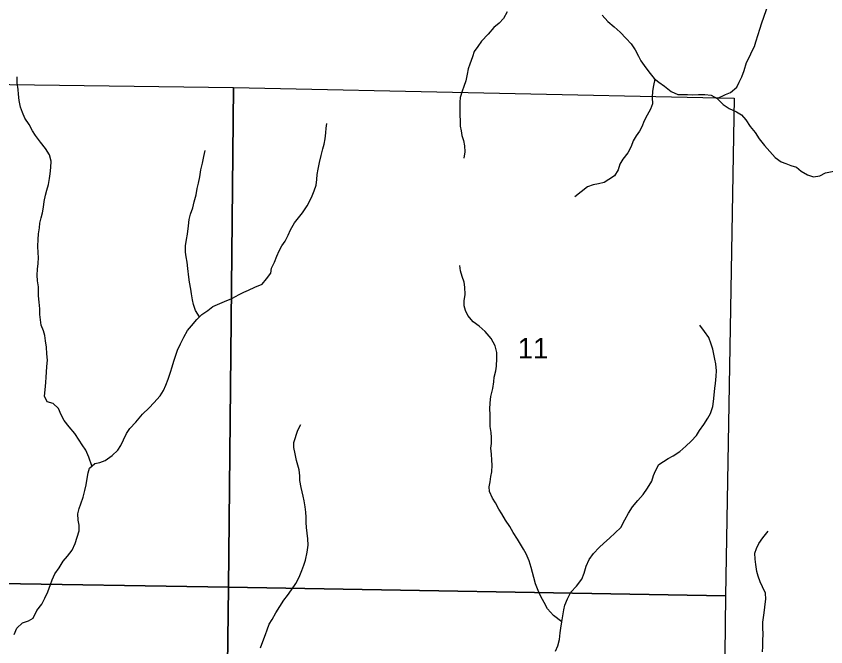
# Model space of a CAD drawing. Extents: x -10 to 158, y 8 to 33.
# Drawn here: x 27.203 to 28.851, y 17.335 to 18.62 of the extents above; entities that cross this region are included whole.
import ezdxf

# ---------------------------------------------------------------- set-up
doc = ezdxf.new("R2010")
doc.units = 0
for name, color, linetype in [('GM_X_Corporation', 7, 'Continuous'), ('GM_X_Minor_River', 7, 'Continuous'), ('GM_X_Section_Text', 7, 'Continuous')]:
    doc.layers.add(name, color=color, linetype=linetype)

msp = doc.modelspace()

# ---------------------------------------------------------------- linework, layer by layer
at = {"layer": 'GM_X_Corporation'}
for points in [[(26.6319, 18.4884), (27.6454, 18.4748), (27.6353, 17.4572), (26.6176, 17.4733)], [(27.6454, 18.4748), (28.6644, 18.4533), (28.647, 17.4394), (27.6353, 17.4572)], [(26.6176, 17.4733), (27.6353, 17.4572), (27.622, 16.4497), (26.6025, 16.4586)], [(27.6353, 17.4572), (28.647, 17.4394), (28.6357, 16.427), (27.622, 16.4497)]]:
    msp.add_lwpolyline(points, close=True, dxfattribs=at)
at = {"layer": 'GM_X_Minor_River'}
for points in [[(28.6301, 18.4525), (28.6472, 18.4605), (28.657, 18.4647), (28.6699, 18.4758), (28.6752, 18.4861), (28.6805, 18.4967), (28.6854, 18.5097), (28.6899, 18.5257), (28.6967, 18.5386), (28.7008, 18.5485), (28.7058, 18.5588), (28.7088, 18.5683), (28.7137, 18.5827), (28.717, 18.5941), (28.7212, 18.6067), (28.7253, 18.6185), (28.7306, 18.6341), (28.7351, 18.644), (28.7427, 18.6558), (28.7529, 18.6691), (28.7658, 18.6806), (28.7771, 18.6874), (28.7885, 18.6928), (28.801, 18.7004)], [(28.2028, 18.6293), (28.1952, 18.6153), (28.1862, 18.6057), (28.1752, 18.5973), (28.1638, 18.5836), (28.1502, 18.5691), (28.1426, 18.5585), (28.1355, 18.5486), (28.1317, 18.5375), (28.1268, 18.5227), (28.1234, 18.5128), (28.1212, 18.5018), (28.1185, 18.4885), (28.114, 18.4771), (28.1106, 18.4672), (28.1069, 18.4546), (28.1061, 18.4451), (28.1062, 18.4185), (28.1066, 18.4071), (28.107, 18.3965), (28.1086, 18.387), (28.1105, 18.3775), (28.1136, 18.3672), (28.1159, 18.3558), (28.1166, 18.3437), (28.114, 18.3311)], [(28.396, 18.6224), (28.4078, 18.6091), (28.4203, 18.5985), (28.4325, 18.5879), (28.4446, 18.575), (28.4549, 18.564), (28.4633, 18.5515), (28.4698, 18.539), (28.4747, 18.5295), (28.4812, 18.52), (28.4907, 18.5068), (28.5018, 18.4931), (28.5113, 18.4859), (28.5231, 18.4776), (28.5364, 18.467), (28.5497, 18.461), (28.5592, 18.4606), (28.5694, 18.4607), (28.5789, 18.4599), (28.5918, 18.4604), (28.6047, 18.4604), (28.618, 18.4593), (28.6301, 18.4525), (28.6423, 18.44), (28.6545, 18.4324), (28.6693, 18.4256), (28.6796, 18.4192), (28.6887, 18.4094), (28.6975, 18.3957), (28.7077, 18.3836), (28.7157, 18.3707), (28.7268, 18.3567), (28.7371, 18.3449), (28.7481, 18.3324), (28.7606, 18.3233), (28.7701, 18.3199), (28.78, 18.3162), (28.7918, 18.3124), (28.8013, 18.3048), (28.8142, 18.2969), (28.826, 18.2927), (28.8393, 18.2951), (28.8506, 18.3012), (28.8742, 18.3058)], [(27.3571, 17.704), (27.351, 17.7218), (27.3445, 17.7358), (27.3369, 17.7468), (27.3312, 17.7567), (27.3224, 17.7699), (27.3106, 17.7836), (27.3004, 17.7965), (27.2946, 17.8082), (27.2889, 17.8211), (27.2779, 17.8313), (27.2661, 17.8347), (27.2604, 17.8461), (27.2619, 17.8587), (27.2634, 17.8742), (27.2637, 17.8849), (27.2644, 17.8951), (27.2655, 17.9065), (27.2663, 17.9195), (27.2655, 17.9324), (27.2643, 17.9461), (27.2628, 17.9586), (27.2612, 17.97), (27.2585, 17.9795), (27.2539, 17.9905), (27.2524, 18.0015), (27.2512, 18.0125), (27.2508, 18.0243), (27.2496, 18.0376), (27.2485, 18.0505), (27.248, 18.0687), (27.2461, 18.0813), (27.2453, 18.0923), (27.2464, 18.1052), (27.2479, 18.1166), (27.2483, 18.1284), (27.2479, 18.1383), (27.2467, 18.152), (27.2474, 18.1653), (27.2485, 18.1767), (27.25, 18.1888), (27.2511, 18.1983), (27.2534, 18.2094), (27.2564, 18.2193), (27.2586, 18.231), (27.2601, 18.2428), (27.2624, 18.2554), (27.2654, 18.2656), (27.2687, 18.2774), (27.271, 18.2896), (27.2717, 18.2991), (27.2736, 18.3117), (27.2739, 18.3246), (27.2709, 18.3375), (27.2625, 18.3504), (27.2526, 18.3636), (27.2419, 18.3769), (27.2358, 18.3868), (27.229, 18.3997), (27.2202, 18.4122), (27.2156, 18.4243), (27.2118, 18.435), (27.2087, 18.4482), (27.2076, 18.4612), (27.2068, 18.4707), (27.2048, 18.4843), (27.2048, 18.4965)], [(28.503, 18.4922), (28.5003, 18.4791), (28.4984, 18.4673), (28.4977, 18.4544), (28.4981, 18.4414), (28.4947, 18.4308), (28.4876, 18.4186), (28.4811, 18.406), (28.4774, 18.3965), (28.4717, 18.3859), (28.4653, 18.3763), (28.4592, 18.3661), (28.4551, 18.3546), (28.4479, 18.3417), (28.4377, 18.3287), (28.4317, 18.3188), (28.4283, 18.3074), (28.4211, 18.2952), (28.4097, 18.2872), (28.3999, 18.2815), (28.3885, 18.2784), (28.3779, 18.2769), (28.3658, 18.2723), (28.3529, 18.2627), (28.3404, 18.2524)], [(27.2039, 17.3733), (27.2156, 17.3844), (27.2282, 17.3886), (27.2376, 17.3939), (27.2448, 17.4092), (27.255, 17.4225), (27.2611, 17.4343), (27.2675, 17.4476), (27.2724, 17.4624), (27.2761, 17.4719), (27.2818, 17.4841), (27.2901, 17.4967), (27.2984, 17.51), (27.3071, 17.5199), (27.3166, 17.5325), (27.323, 17.5458), (27.3313, 17.5716), (27.3313, 17.5834), (27.329, 17.5937), (27.3282, 17.6062), (27.3312, 17.6176), (27.3346, 17.6271), (27.3391, 17.6404), (27.3425, 17.6537), (27.3455, 17.6655), (27.3473, 17.6784), (27.3496, 17.6899), (27.3522, 17.6997), (27.3628, 17.7089), (27.3734, 17.7112), (27.3837, 17.715), (27.3985, 17.725), (27.4098, 17.736), (27.4162, 17.7459), (27.4211, 17.757), (27.4272, 17.7703), (27.434, 17.7802), (27.4465, 17.7931), (27.4597, 17.8095), (27.4733, 17.8221), (27.4828, 17.8324), (27.4957, 17.8465), (27.5025, 17.8575), (27.5074, 17.8682), (27.5126, 17.8811), (27.5172, 17.8948), (27.5202, 17.9062), (27.5236, 17.9173), (27.5277, 17.9298), (27.5311, 17.9397), (27.5375, 17.953), (27.5439, 17.966), (27.5518, 17.9797), (27.5598, 17.9896), (27.5704, 18.0025), (27.581, 18.0128), (27.5931, 18.0208), (27.6029, 18.0285), (27.6173, 18.0346), (27.6272, 18.0388), (27.6416, 18.0453), (27.6568, 18.0533), (27.6662, 18.0583), (27.6757, 18.0621), (27.6886, 18.0679), (27.7034, 18.074), (27.7128, 18.0855), (27.7212, 18.0965), (27.723, 18.1071), (27.7287, 18.1193), (27.7336, 18.1315), (27.7381, 18.1425), (27.7438, 18.1524), (27.7502, 18.162), (27.7566, 18.1741), (27.7615, 18.1848), (27.7695, 18.1993), (27.7778, 18.2092), (27.7861, 18.2198), (27.7955, 18.2339), (27.8008, 18.2442), (27.8057, 18.2545), (27.8095, 18.2644), (27.8133, 18.2758), (27.8148, 18.2872), (27.8155, 18.2978), (27.8174, 18.3089), (27.8204, 18.3222), (27.8241, 18.3363), (27.8275, 18.3503), (27.8297, 18.3598), (27.832, 18.3705), (27.8335, 18.3827), (27.8338, 18.3922), (27.8353, 18.4017)], [(27.5758, 18.0077), (27.5677, 18.0204), (27.5639, 18.0329), (27.5619, 18.0424), (27.56, 18.0546), (27.5581, 18.0641), (27.5558, 18.0785), (27.5546, 18.0887), (27.5526, 18.1062), (27.5507, 18.1188), (27.5492, 18.1298), (27.5476, 18.1396), (27.5476, 18.1522), (27.5498, 18.1655), (27.5517, 18.1761), (27.5536, 18.1929), (27.5547, 18.2062), (27.5577, 18.2168), (27.5626, 18.2298), (27.5652, 18.2419), (27.569, 18.256), (27.5712, 18.2693), (27.5742, 18.2803), (27.5768, 18.2929), (27.5791, 18.3073), (27.5821, 18.321), (27.5851, 18.3343), (27.5873, 18.3465)], [(28.3138, 17.3861), (28.2971, 17.3995), (28.2849, 17.4132), (28.2777, 17.4257), (28.2712, 17.4378), (28.2659, 17.45), (28.2605, 17.4636), (28.2567, 17.4769), (28.2544, 17.4872), (28.2513, 17.4974), (28.2471, 17.5107), (28.241, 17.5247), (28.2357, 17.5346), (28.2299, 17.5445), (28.2235, 17.5547), (28.2147, 17.5687), (28.2082, 17.5809), (28.1991, 17.5934), (28.1915, 17.6063), (28.1857, 17.6161), (28.1785, 17.629), (28.1724, 17.6385), (28.1667, 17.6518), (28.1659, 17.6617), (28.1678, 17.6715), (28.1696, 17.6822), (28.1715, 17.6917), (28.1722, 17.7054), (28.1711, 17.7156), (28.1703, 17.7278), (28.1695, 17.7399), (28.1706, 17.7498), (28.1706, 17.762), (28.1698, 17.7719), (28.1682, 17.7844), (28.1678, 17.7954), (28.1678, 17.8095), (28.1674, 17.8197), (28.1677, 17.8323), (28.1696, 17.8456), (28.1733, 17.8619), (28.1752, 17.8752), (28.1763, 17.8847), (28.1793, 17.8977), (28.1808, 17.9072), (28.1815, 17.9228), (28.1815, 17.9349), (28.178, 17.9486), (28.17, 17.9638), (28.1579, 17.9778), (28.1457, 17.9884), (28.1335, 17.9975), (28.1225, 18.0108), (28.1179, 18.0206), (28.1148, 18.0301), (28.1152, 18.0404), (28.117, 18.0533), (28.1162, 18.0685), (28.1151, 18.0784), (28.1109, 18.0898), (28.1074, 18.1015), (28.1063, 18.1122)], [(28.3319, 17.4468), (28.344, 17.459), (28.3546, 17.473), (28.3591, 17.4856), (28.3636, 17.4997), (28.3693, 17.5134), (28.378, 17.5255), (28.3897, 17.5381), (28.3996, 17.5469), (28.4109, 17.5568), (28.4227, 17.5675), (28.434, 17.5789), (28.4423, 17.5941), (28.4495, 17.6078), (28.4578, 17.6208), (28.4684, 17.6334), (28.4794, 17.6455), (28.4884, 17.6589), (28.4968, 17.673), (28.5005, 17.6844), (28.5043, 17.6943), (28.5115, 17.7068), (28.5209, 17.7133), (28.5304, 17.719), (28.5406, 17.7244), (28.5543, 17.7336), (28.566, 17.7446), (28.5774, 17.7542), (28.588, 17.766), (28.5944, 17.7762), (28.6031, 17.7881), (28.611, 17.801), (28.6167, 17.8109), (28.6212, 17.825), (28.6227, 17.8356), (28.6238, 17.8485), (28.6253, 17.8622), (28.6264, 17.8721), (28.6282, 17.8869), (28.6286, 17.8976), (28.6274, 17.912), (28.6251, 17.9215), (28.6236, 17.9314), (28.6213, 17.9416), (28.6182, 17.9519), (28.6129, 17.9656), (28.6041, 17.9781), (28.595, 17.991)], [(27.793, 17.5997), (27.7923, 17.6099), (27.7915, 17.6206), (27.7895, 17.6327), (27.7872, 17.6426), (27.7834, 17.6604), (27.7803, 17.6745), (27.7803, 17.684), (27.7788, 17.6958), (27.7761, 17.7053), (27.7734, 17.7151), (27.7711, 17.7288), (27.768, 17.7417), (27.768, 17.7516), (27.7763, 17.7767), (27.7827, 17.7885)], [(27.7004, 17.3335), (27.7053, 17.346), (27.7105, 17.3609), (27.7139, 17.3704), (27.7181, 17.3818), (27.7237, 17.3913), (27.7313, 17.405), (27.7396, 17.4175), (27.7476, 17.4305), (27.7551, 17.44), (27.7634, 17.4514), (27.7721, 17.4648), (27.7789, 17.4773), (27.7842, 17.491), (27.7887, 17.5017), (27.7917, 17.5123), (27.7955, 17.5286), (27.7974, 17.5427), (27.7966, 17.5552), (27.7954, 17.567), (27.7942, 17.5784), (27.7934, 17.589), (27.793, 17.5997)], [(28.7227, 17.3253), (28.723, 17.3363), (28.7234, 17.3477), (28.7237, 17.3621), (28.7233, 17.3735), (28.7233, 17.3857), (28.7248, 17.3998), (28.7266, 17.41), (28.7281, 17.4226), (28.7292, 17.4328), (28.7284, 17.4446), (28.7227, 17.4579), (28.7174, 17.4677), (28.7139, 17.4791), (28.7112, 17.489), (28.7089, 17.5034), (28.7074, 17.514), (28.707, 17.5266), (28.71, 17.5361), (28.7149, 17.546), (28.7232, 17.5578), (28.7338, 17.5711)], [(28.3011, 17.3266), (28.306, 17.3373), (28.3094, 17.3506), (28.3105, 17.3639), (28.3116, 17.3738), (28.3138, 17.3863), (28.3161, 17.3985), (28.3179, 17.411), (28.3198, 17.4205), (28.3255, 17.4334), (28.3319, 17.4468)], [(27.1986, 17.3608), (27.2039, 17.3733)]]:
    msp.add_lwpolyline(points, dxfattribs=at)

# ---------------------------------------------------------------- texts
at = {"layer": 'GM_X_Section_Text'}
msp.add_text('11', height=0.04186, rotation=0, dxfattribs=at).set_placement((28.2241, 17.9229))

doc.saveas('drawing.dxf')
